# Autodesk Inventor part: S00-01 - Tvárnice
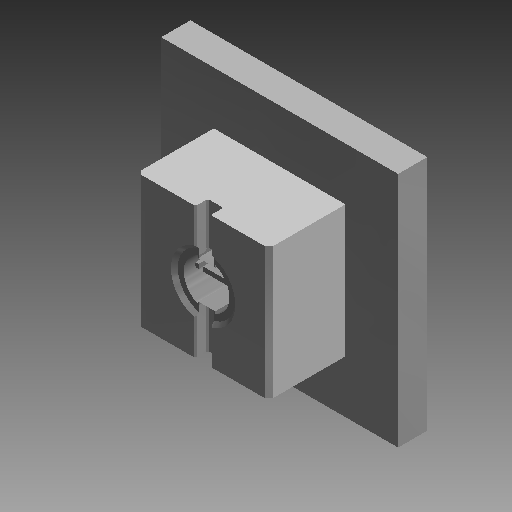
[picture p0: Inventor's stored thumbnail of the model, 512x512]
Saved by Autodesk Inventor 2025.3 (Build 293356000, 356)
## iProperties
Part Number: S00-01 - Tvárnice
Material: Generický
Document SubType Name: Modelování
Designer: Patrik
Appearance: Výchozí
Description: Tvárnice
Author: Patrik
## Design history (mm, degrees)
node "Sestava - mold design_MODEL - mk4 Blenddoor Tab v4_2_CR_Base"
node "Objemová tělesa"
node "Povrchová tělesa"
feature "Těleso7::Sestava - mold design_MODEL - mk4 Blenddoor Tab v4_"
tag "Prvek štítků1"
node "Těleso7"
feature "Sestava - mold design_MODEL - mk4 Blenddoor Tab v4_2_CR_Base"
